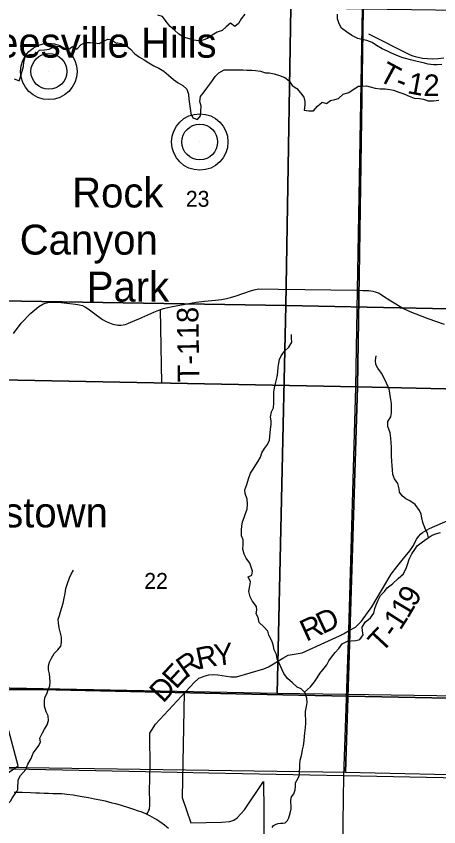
# Model space of a CAD drawing. Extents: x -19.9 to 41.9, y 0 to 32.3.
# Drawn here: x 6.203 to 7.317, y 17.59 to 19.727 of the extents above; entities that cross this region are included whole.
import ezdxf

# ---------------------------------------------------------------- set-up
doc = ezdxf.new("R2010")
doc.units = 0
for name, color, linetype in [('GM_X_Corporation', 7, 'Continuous'), ('GM_X_County', 7, 'Continuous'), ('GM_X_Major_Lake', 7, 'Continuous'), ('GM_X_Minor_River', 7, 'Continuous'), ('GM_X_Section', 7, 'Continuous'), ('GM_X_Section_Text', 7, 'Continuous'), ('GM_X_State_Route', 7, 'Continuous'), ('GM_X_Township', 7, 'Continuous'), ('GM_X_Township_Road', 7, 'Continuous'), ('GM_X_Township_Road_Text', 7, 'Continuous'), ('GM_X_Unincorporated', 7, 'Continuous'), ('GM_X_Unincorporated_Location', 7, 'Continuous'), ('GM_X_Unincorporated_Text', 7, 'Continuous')]:
    doc.layers.add(name, color=color, linetype=linetype)

msp = doc.modelspace()

# ---------------------------------------------------------------- linework, layer by layer
at = {"layer": 'GM_X_Corporation'}
for points in [[(8.9, 17.8974), (8.9, 20.9), (2.1, 20.9), (2.1, 17.918), (2.4715, 17.9106), (2.973, 17.9007), (3.7505, 17.884), (3.984, 17.879), (4.2613, 17.8672), (4.9169, 17.8392), (5.0192, 17.8403), (5.0257, 17.9637), (5.4954, 17.9559), (5.761, 17.9543), (5.9048, 17.9534), (6.2397, 17.9517), (6.2497, 17.9517), (6.3069, 17.9505), (6.7, 17.9422), (6.9468, 17.937), (7.3858, 17.9277), (7.5529, 17.9242), (7.9072, 17.9171)], [(5.9183, 19.976), (6.9305, 19.9596), (6.9135, 18.9637), (5.8941, 18.9811)], [(7.9591, 19.9393), (7.944, 18.9426), (6.9135, 18.9637), (6.9305, 19.9596)], [(5.8941, 18.9811), (6.9135, 18.9637), (6.8905, 17.9411), (5.8771, 17.961)], [(6.9135, 18.9637), (7.944, 18.9426), (7.9129, 17.9261), (6.8905, 17.9411)], [(2.1, 17.918), (2.1, 14.1), (8.9, 14.1), (8.9, 17.8974), (7.9072, 17.9171), (7.5529, 17.9242), (7.3858, 17.9277), (6.9468, 17.937), (6.7, 17.9422), (6.3069, 17.9505), (6.2497, 17.9517), (6.2397, 17.9517), (5.9048, 17.9534), (5.761, 17.9543), (5.4954, 17.9559), (5.0257, 17.9637), (5.0192, 17.8403), (4.9169, 17.8392), (4.2613, 17.8672), (3.984, 17.879), (3.7505, 17.884), (2.973, 17.9007), (2.4715, 17.9106)]]:
    msp.add_lwpolyline(points, close=True, dxfattribs=at)
for points in [[(2.973, 17.9007), (3.7505, 17.884), (3.984, 17.879), (4.2613, 17.8672), (4.9169, 17.8392), (5.0192, 17.8403), (5.0257, 17.9637), (5.4954, 17.9559), (5.761, 17.9543), (5.9048, 17.9534), (6.2397, 17.9517), (6.2497, 17.9517), (6.3069, 17.9505), (6.7, 17.9422), (6.9468, 17.937), (7.3858, 17.9277), (7.5529, 17.9242), (7.9072, 17.9171), (7.9208, 18.3004), (7.9387, 18.9418), (7.9433, 19.1981), (7.9567, 19.9408), (7.9833, 20.9), (2.1, 20.9)], [(7.9012, 17.4524), (7.9072, 17.9171), (7.5529, 17.9242), (7.3858, 17.9277), (6.9468, 17.937), (6.7, 17.9422), (6.3069, 17.9505), (6.2497, 17.9517), (6.2397, 17.9517), (5.9048, 17.9534), (5.761, 17.9543), (5.4954, 17.9559), (5.0257, 17.9637), (5.0192, 17.8403), (4.9169, 17.8392), (4.2613, 17.8672), (3.984, 17.879), (3.7505, 17.884), (2.973, 17.9007), (2.4715, 17.9106), (2.1, 17.918), (2.1, 14.1)], [(5.8562, 17.5075), (6.2079, 17.7506), (6.1536, 17.9521), (6.2743, 17.9513), (6.3872, 17.9486), (6.6452, 17.9441), (6.6403, 17.6667), (6.6627, 17.6004), (6.7437, 17.602), (6.7663, 17.604), (6.776, 17.6074), (6.7848, 17.6135), (6.8042, 17.6347), (6.8543, 17.709), (6.8558, 17.6308), (6.8557, 17.4298)]]:
    msp.add_lwpolyline(points, dxfattribs=at)
at = {"layer": 'GM_X_County'}
msp.add_lwpolyline([(8.9, 17.6915), (8.8006, 17.694), (8.0736, 17.7036), (7.0652, 17.7237), (6.7109, 17.7307), (6.5438, 17.7343), (6.1048, 17.7436), (5.8581, 17.7488), (5.4649, 17.757), (5.4078, 17.7582), (5.3977, 17.7582), (5.0628, 17.7599), (4.9191, 17.7608), (4.6534, 17.7624), (4.1838, 17.7703), (4.1772, 17.6468), (4.0749, 17.6457), (3.4193, 17.6737), (3.142, 17.6855), (2.9085, 17.6906), (2.1311, 17.7073), (2.1, 17.7079)], dxfattribs=at)
at = {"layer": 'GM_X_Major_Lake'}
for points in [[(6.8058, 19.7324), (6.7961, 19.7201), (6.7891, 19.7078), (6.7794, 19.6993), (6.7675, 19.7079), (6.7566, 19.6986), (6.7453, 19.6885), (6.7321, 19.6841), (6.7197, 19.6763), (6.7069, 19.6678), (6.6948, 19.6638), (6.6831, 19.6613), (6.6712, 19.6638), (6.6583, 19.667), (6.6445, 19.6713), (6.6318, 19.6794), (6.6199, 19.6895), (6.6083, 19.6999), (6.5982, 19.713), (6.5881, 19.7257), (6.5759, 19.7293)], [(7.1011, 19.6683), (7.0873, 19.676), (7.0738, 19.6853), (7.0604, 19.6953), (7.0537, 19.7069), (7.0497, 19.7194), (7.0499, 19.7319)], [(6.1977, 19.5618), (6.2108, 19.5563), (6.2147, 19.5693), (6.2187, 19.5819), (6.2223, 19.5941), (6.2229, 19.6062), (6.2261, 19.6192), (6.2377, 19.6254), (6.2533, 19.6257), (6.2645, 19.6369), (6.2775, 19.6382), (6.29, 19.6396), (6.3043, 19.6466), (6.3157, 19.6472), (6.328, 19.6398), (6.339, 19.6377), (6.3514, 19.647), (6.363, 19.6393), (6.3742, 19.6524), (6.3855, 19.6571), (6.398, 19.6573), (6.4083, 19.6563), (6.4213, 19.655), (6.4326, 19.6605), (6.4446, 19.6657), (6.4542, 19.6647), (6.4672, 19.6558)], [(7.3246, 19.5996), (7.3125, 19.5986), (7.303, 19.5984), (7.2885, 19.6001), (7.279, 19.603), (7.2679, 19.6058), (7.2557, 19.6083), (7.242, 19.6118), (7.229, 19.6147), (7.2194, 19.6175), (7.2045, 19.6241), (7.1919, 19.6296), (7.1811, 19.6343), (7.1677, 19.6406), (7.1528, 19.6494), (7.1408, 19.6576), (7.1274, 19.6623), (7.1149, 19.6655), (7.1026, 19.6679), (7.1011, 19.6683)], [(6.4672, 19.6558), (6.4695, 19.6562), (6.4798, 19.6549), (6.4924, 19.649), (6.5044, 19.6401), (6.5152, 19.6278), (6.5279, 19.6189), (6.5402, 19.6115), (6.5525, 19.6037), (6.5656, 19.5956), (6.579, 19.5894), (6.592, 19.5816), (6.6044, 19.5712), (6.6175, 19.5597), (6.6298, 19.5508), (6.6421, 19.5438), (6.6529, 19.5341), (6.6569, 19.5209), (6.6579, 19.5076), (6.6592, 19.4955), (6.6617, 19.4834), (6.6631, 19.4701), (6.6686, 19.4588), (6.6808, 19.4541), (6.6883, 19.4637), (6.6896, 19.4763), (6.6905, 19.4892), (6.6869, 19.502), (6.6886, 19.5146), (6.6986, 19.5273), (6.7079, 19.5403), (6.7183, 19.5545), (6.7276, 19.5676), (6.7365, 19.5776), (6.7505, 19.585), (6.7634, 19.5849), (6.7756, 19.5854), (6.7877, 19.5849), (6.8003, 19.5851), (6.8106, 19.5841), (6.8239, 19.584), (6.8334, 19.5838), (6.8463, 19.5817), (6.8597, 19.5777), (6.8696, 19.5775), (6.883, 19.5743), (6.8967, 19.57), (6.9109, 19.5649), (6.922, 19.556), (6.9306, 19.5437), (6.9421, 19.5359), (6.9518, 19.525), (6.9611, 19.5131), (6.9632, 19.5017), (6.9638, 19.4922), (6.9621, 19.4793), (6.9739, 19.4768), (6.9861, 19.4774), (6.9969, 19.4894), (7.0093, 19.5002), (7.0211, 19.4962), (7.0309, 19.5044), (7.0426, 19.5068), (7.0524, 19.5096), (7.0648, 19.5212), (7.0792, 19.5257), (7.0912, 19.5338), (7.1047, 19.542), (7.1158, 19.5422), (7.126, 19.5427), (7.1359, 19.5406), (7.1493, 19.5367), (7.1619, 19.5354), (7.1756, 19.5349), (7.1874, 19.5332), (7.1969, 19.5318), (7.2114, 19.5267), (7.2248, 19.522), (7.2382, 19.5154), (7.2516, 19.5107), (7.2661, 19.5098), (7.276, 19.5081), (7.289, 19.5037), (7.3023, 19.5036), (7.3167, 19.5057)]]:
    msp.add_lwpolyline(points, dxfattribs=at)
at = {"layer": 'GM_X_Minor_River'}
for points in [[(6.9499, 17.7275), (6.9502, 17.7529), (6.9512, 17.7651), (6.9545, 17.778), (6.9578, 17.7925), (6.9604, 17.8035), (6.9618, 17.8164), (6.9624, 17.8278), (6.9635, 17.8373), (6.9657, 17.8518), (6.9663, 17.8624), (6.9659, 17.8731), (6.965, 17.8825), (6.9657, 17.8939), (6.9682, 17.9065), (6.9693, 17.9171), (6.9688, 17.9289), (6.9645, 17.9425), (6.9538, 17.9531), (6.9435, 17.9579), (6.9309, 17.9692), (6.9179, 17.9805), (6.9086, 17.9941), (6.8955, 18.0213), (6.8909, 18.0323), (6.8885, 18.0436), (6.8831, 18.0561), (6.8803, 18.0698), (6.8764, 18.08), (6.8687, 18.0951), (6.8656, 18.1057), (6.8552, 18.117), (6.8433, 18.1279), (6.8406, 18.1416), (6.8352, 18.1514), (6.837, 18.1609), (6.8365, 18.1708), (6.8246, 18.1851), (6.8196, 18.1961), (6.8161, 18.2101), (6.819, 18.2249), (6.8204, 18.2352), (6.8142, 18.2484), (6.8241, 18.2534), (6.8255, 18.2633), (6.822, 18.2743), (6.8189, 18.2845), (6.8085, 18.2977), (6.8039, 18.3083), (6.7999, 18.3212), (6.8014, 18.3337), (6.8009, 18.3462), (6.7966, 18.3565), (6.7965, 18.3724), (6.7975, 18.3823), (6.7997, 18.3937), (6.8034, 18.4055), (6.8071, 18.4154), (6.8112, 18.4272), (6.8126, 18.4401), (6.8114, 18.4534), (6.8063, 18.4682), (6.8051, 18.4784), (6.8103, 18.4917), (6.8155, 18.5066), (6.8203, 18.5218), (6.827, 18.5325), (6.8345, 18.5443), (6.8405, 18.5539), (6.8469, 18.5642), (6.8506, 18.5752), (6.857, 18.5867), (6.8649, 18.5974), (6.8701, 18.6088), (6.8711, 18.6187), (6.8718, 18.6282), (6.8733, 18.638), (6.8751, 18.6502), (6.8746, 18.6597), (6.873, 18.6695), (6.8755, 18.6836), (6.8808, 18.6939), (6.8822, 18.7068), (6.8817, 18.7209), (6.8819, 18.7353), (6.8834, 18.7467), (6.887, 18.7615), (6.8907, 18.7756), (6.8921, 18.7885), (6.8935, 18.8011), (6.8953, 18.8117), (6.8968, 18.8212), (6.9009, 18.8311), (6.9103, 18.8433), (6.9216, 18.8541), (6.9294, 18.867), (6.9282, 18.8776), (6.9285, 18.8879)], [(7.2898, 18.352), (7.2865, 18.363), (7.2804, 18.3762), (7.2742, 18.3917), (7.2718, 18.4038), (7.2702, 18.4137), (7.2659, 18.4235), (7.2544, 18.439), (7.2399, 18.4491), (7.2296, 18.454), (7.22, 18.4619), (7.2135, 18.4717), (7.2119, 18.4811), (7.2087, 18.4944), (7.1995, 18.5072), (7.1956, 18.5186), (7.1944, 18.5307), (7.1939, 18.5425), (7.1927, 18.5527), (7.1918, 18.5679), (7.1924, 18.5797), (7.1923, 18.5918), (7.1915, 18.6017), (7.1906, 18.6146), (7.1882, 18.6279), (7.1824, 18.6449), (7.1827, 18.6582), (7.1905, 18.6708), (7.192, 18.681), (7.1919, 18.6943), (7.1918, 18.7057), (7.1893, 18.7216), (7.1874, 18.7326), (7.1854, 18.7444), (7.1788, 18.7591), (7.1726, 18.7724), (7.1653, 18.7852), (7.156, 18.7988), (7.151, 18.8086), (7.1502, 18.8192), (7.152, 18.831)], [(6.9628, 17.9442), (6.9781, 17.9586), (6.9886, 17.9716), (6.9965, 17.9827), (7.0032, 17.9937), (7.0111, 18.0037), (7.0213, 18.017), (7.0272, 18.0273), (7.0336, 18.0369), (7.0438, 18.0488), (7.0528, 18.0595), (7.0622, 18.0717), (7.0758, 18.079), (7.0861, 18.0799), (7.0982, 18.0807), (7.1084, 18.0835), (7.1171, 18.0957), (7.1159, 18.1059), (7.1143, 18.1158), (7.1225, 18.1295), (7.1365, 18.1407), (7.1455, 18.1529), (7.1484, 18.1651), (7.1517, 18.1746), (7.1566, 18.1872), (7.1629, 18.1998), (7.1735, 18.2097), (7.181, 18.2193), (7.1946, 18.23), (7.2097, 18.2442), (7.2236, 18.2569), (7.2311, 18.2732), (7.2348, 18.2839), (7.2389, 18.295), (7.246, 18.3091), (7.2531, 18.3205), (7.2599, 18.3301), (7.2734, 18.3408), (7.2863, 18.3497), (7.2991, 18.3581), (7.3112, 18.3628), (7.3211, 18.3655)], [(6.2281, 17.7408), (6.2331, 17.7545), (6.2424, 17.7697), (6.2472, 17.7834), (6.2555, 17.7941), (6.2626, 17.8037), (6.2664, 17.8136), (6.2655, 17.8231), (6.2719, 17.8376), (6.2775, 17.8471), (6.2846, 17.8585), (6.2875, 17.87), (6.2867, 17.8825), (6.282, 17.8927), (6.2773, 17.9078), (6.2772, 17.9207), (6.2783, 17.931), (6.2839, 17.9405), (6.2872, 17.9508), (6.2917, 17.9615), (6.292, 17.9717), (6.2911, 17.9831), (6.2903, 17.993), (6.2883, 18.0032), (6.2878, 18.0142), (6.2908, 18.0237), (6.296, 18.034), (6.3031, 18.0462), (6.3122, 18.0558), (6.3201, 18.0657), (6.3226, 18.076), (6.3222, 18.0897), (6.319, 18.1033), (6.3163, 18.1139), (6.3143, 18.1264), (6.3138, 18.1367), (6.3167, 18.147), (6.3197, 18.1565), (6.3234, 18.1675), (6.3263, 18.1793), (6.3296, 18.1923), (6.3318, 18.2048), (6.3336, 18.2181), (6.3377, 18.2314), (6.3433, 18.2459), (6.3477, 18.2554), (6.3541, 18.2661)], [(6.1152, 17.5833), (6.1257, 17.5938), (6.1316, 17.6007), (6.1398, 17.6092), (6.1473, 17.6173), (6.157, 17.6285), (6.17, 17.6409), (6.1813, 17.651), (6.1876, 17.6575), (6.192, 17.6652), (6.1976, 17.6729), (6.2043, 17.6829), (6.2069, 17.6879), (6.2075, 17.6929), (6.2075, 17.6986), (6.2078, 17.7043), (6.2084, 17.7135), (6.2145, 17.7252), (6.2281, 17.7408)], [(6.8777, 17.5876), (6.881, 17.5929), (6.8881, 17.5969), (6.8934, 17.5981), (6.8991, 17.5989), (6.9055, 17.5994), (6.9119, 17.6006), (6.9183, 17.6065), (6.9216, 17.613), (6.9252, 17.6256), (6.9273, 17.6367), (6.9276, 17.6447), (6.9267, 17.6542), (6.9266, 17.6595), (6.9288, 17.6687), (6.9343, 17.6768), (6.938, 17.6868), (6.9393, 17.6971), (6.9388, 17.7054), (6.9424, 17.7114), (6.9472, 17.7194), (6.9499, 17.7275)]]:
    msp.add_lwpolyline(points, dxfattribs=at)
at = {"layer": 'GM_X_Section'}
for points in [[(7.1171, 19.7458), (7.1021, 18.7492), (6.0716, 18.7702), (6.0885, 19.7661)], [(7.1171, 19.7458), (8.1335, 19.7322), (8.1079, 18.7263), (7.1021, 18.7492)], [(6.0716, 18.7702), (7.1021, 18.7492), (7.0709, 17.7326), (6.0485, 17.7476)], [(7.1021, 18.7492), (8.1079, 18.7263), (8.0871, 17.7103), (7.0709, 17.7326)]]:
    msp.add_lwpolyline(points, close=True, dxfattribs=at)
at = {"layer": 'GM_X_State_Route'}
for points in [[(6.1953, 18.8899), (6.2159, 18.9171), (6.2412, 18.9434), (6.2625, 18.9613), (6.2734, 18.9674), (6.2791, 18.9703), (6.2862, 18.9716), (6.2947, 18.9725), (6.3133, 18.9724), (6.3442, 18.9693), (6.3592, 18.9675), (6.3695, 18.9659), (6.3778, 18.9636), (6.3858, 18.9599), (6.3921, 18.9554), (6.3994, 18.9497), (6.4066, 18.9443), (6.4299, 18.9275), (6.4395, 18.9218), (6.4483, 18.918), (6.4571, 18.9147), (6.4705, 18.9122), (6.4787, 18.9124), (6.4846, 18.9129), (6.491, 18.9143), (6.4988, 18.9171), (6.526, 18.9287), (6.5659, 18.9465), (6.5835, 18.9535), (6.5908, 18.956), (6.5983, 18.958), (6.6145, 18.9615), (6.6775, 18.9731), (6.6987, 18.9758), (6.728, 18.9784), (6.7439, 18.9802), (6.757, 18.9821), (6.768, 18.9847), (6.783, 18.9892), (6.8207, 19.0023), (6.8298, 19.0055), (6.8415, 19.0078), (6.8942, 19.0068), (7.1015, 19.004), (7.1167, 19.0036), (7.1323, 19.0033), (7.1432, 19.0015), (7.1491, 19.0001), (7.1592, 18.9961), (7.1684, 18.9903), (7.1902, 18.9762), (7.2232, 18.9563), (7.24, 18.9479), (7.288, 18.93), (7.3309, 18.9144)], [(6.1974, 17.6809), (6.2066, 17.681), (6.2182, 17.6809), (6.2406, 17.6801), (6.2548, 17.6795), (6.2646, 17.6791), (6.2769, 17.6784), (6.2875, 17.678), (6.2993, 17.6777), (6.3176, 17.6773), (6.323, 17.6771), (6.3298, 17.6766), (6.3361, 17.676), (6.3526, 17.6737), (6.3613, 17.6724), (6.3771, 17.6698), (6.3932, 17.6668), (6.4093, 17.6638), (6.4237, 17.6609), (6.4373, 17.6578), (6.4551, 17.6533), (6.4647, 17.6507), (6.4797, 17.6465), (6.4992, 17.6406), (6.5097, 17.6372), (6.5247, 17.632), (6.531, 17.6297), (6.5432, 17.6248), (6.547, 17.6231), (6.5488, 17.6223), (6.5537, 17.6199), (6.5603, 17.6164), (6.5667, 17.6128), (6.5736, 17.6086), (6.5814, 17.6036), (6.5875, 17.5994), (6.5934, 17.5949), (6.5997, 17.5899), (6.6044, 17.5857)]]:
    msp.add_lwpolyline(points, dxfattribs=at)
at = {"layer": 'GM_X_Township'}
for p, q in [((7.1147, 19.7474), (7.1013, 19.0046)), ((7.1013, 19.0046), (7.0967, 18.7483)), ((7.0967, 18.7483), (7.0788, 18.1069)), ((7.0788, 18.1069), (7.0652, 17.7237)), ((7.0652, 17.7237), (7.0592, 17.259))]:
    msp.add_line(p, q, dxfattribs=at)
at = {"layer": 'GM_X_Township_Road'}
msp.add_line((6.5863, 18.7592), (6.5835, 18.9535), dxfattribs=at)
for points in [[(7.131, 19.6801), (7.2416, 19.6245), (7.2478, 19.622), (7.2543, 19.62), (7.2735, 19.6161), (7.2998, 19.6143), (7.315, 19.6147), (7.3299, 19.6167)], [(7.0655, 18.0988), (7.079, 18.1064), (7.0967, 18.1164), (7.1125, 18.1319), (7.14, 18.1696), (7.1912, 18.2556), (7.2064, 18.2751), (7.2236, 18.2969), (7.2406, 18.3174), (7.2501, 18.3312), (7.2576, 18.3481), (7.2636, 18.3555), (7.2681, 18.3612), (7.2738, 18.3658), (7.292, 18.3762), (7.3866, 18.4176)], [(6.5558, 17.7414), (6.555, 17.8367), (6.5696, 17.86), (6.6729, 17.9713), (6.6811, 17.979), (6.6841, 17.9814), (6.6891, 17.9836), (6.6984, 17.9866), (6.7107, 17.9899), (6.7228, 17.9908), (6.7343, 17.9906), (6.7686, 17.9852), (6.7768, 17.9848), (6.7831, 17.9854), (6.8559, 18.0065), (6.868, 18.0116), (6.9054, 18.034), (6.9197, 18.0418), (6.9566, 18.0482), (7.055, 18.0935), (7.0586, 18.0952), (7.0613, 18.0964), (7.0655, 18.0988)], [(6.547, 17.6231), (6.5496, 17.6271), (6.5518, 17.631), (6.5528, 17.6332), (6.5538, 17.6365), (6.5544, 17.6399), (6.5547, 17.6434), (6.5548, 17.6486), (6.5545, 17.6926), (6.5546, 17.7086), (6.5548, 17.723), (6.5553, 17.7331), (6.5558, 17.7414)]]:
    msp.add_lwpolyline(points, dxfattribs=at)
at = {"layer": 'GM_X_Unincorporated'}
for centre, radius in [((6.2889, 19.5811), 0.0744), ((6.2889, 19.5811), 0.0472), ((6.6866, 19.395), 0.0744), ((6.6866, 19.395), 0.0472)]:
    msp.add_circle(centre, radius, dxfattribs=at)
at = {"layer": 'GM_X_Unincorporated_Location'}
for p, q in [((6.2889, 19.5811), (6.2889, 19.5811)), ((6.6866, 19.395), (6.6866, 19.395))]:
    msp.add_line(p, q, dxfattribs=at)

# ---------------------------------------------------------------- texts
at = {"layer": 'GM_X_Section_Text'}
for s, p in [('23', (6.6499, 19.2242)), ('22', (6.5403, 18.217))]:
    msp.add_text(s, height=0.04186, rotation=0, dxfattribs=at).set_placement(p)
at = {"layer": 'GM_X_Township_Road_Text'}
for s, height, rotation, p in [('T', 0.0568, 331.7902, (7.1542, 19.559)), ('1', 0.0568, 349.6204, (7.2315, 19.524)), ('2', 0.0568, 358.8868, (7.2759, 19.5167)), ('-', 0.0568, 338.3264, (7.1981, 19.536)), ('T-118', 0.05682, 90.8431, (6.6856, 18.7622)), ('9', 0.0568, 58.7962, (7.253, 18.1668)), ('1', 0.0568, 59.3217, (7.2353, 18.1368)), ('D', 0.0568, 25.2493, (7.0104, 18.0968)), ('R', 0.0568, 24.4561, (6.9672, 18.0772)), ('1', 0.0568, 57.3696, (7.2153, 18.1055)), ('T', 0.0568, 47.0944, (7.1662, 18.0464)), ('-', 0.0568, 55.1579, (7.2006, 18.0844)), ('R', 0.0568, 11.7382, (6.683, 18.0043)), ('Y', 0.0568, 6.4979, (6.7273, 18.0136)), ('R', 0.0568, 35.4569, (6.6506, 17.9797)), ('E', 0.0568, 47.2036, (6.624, 17.9505)), ('D', 0.0568, 47.3975, (6.5902, 17.9138))]:
    msp.add_text(s, height=height, rotation=rotation, dxfattribs=at).set_placement(p)
at = {"layer": 'GM_X_Unincorporated_Text'}
for s, height, p in [('Leesville Hills', 0.078977, (6.0912, 19.6174)), ('Rock', 0.07898, (6.3503, 19.2224)), ('Canyon', 0.07898, (6.212, 19.0982)), ('Park', 0.07898, (6.3887, 18.9741)), ('New Hagerstown', 0.078977, (5.6403, 18.3791))]:
    msp.add_text(s, height=height, rotation=0, dxfattribs=at).set_placement(p)

doc.saveas('drawing.dxf')
